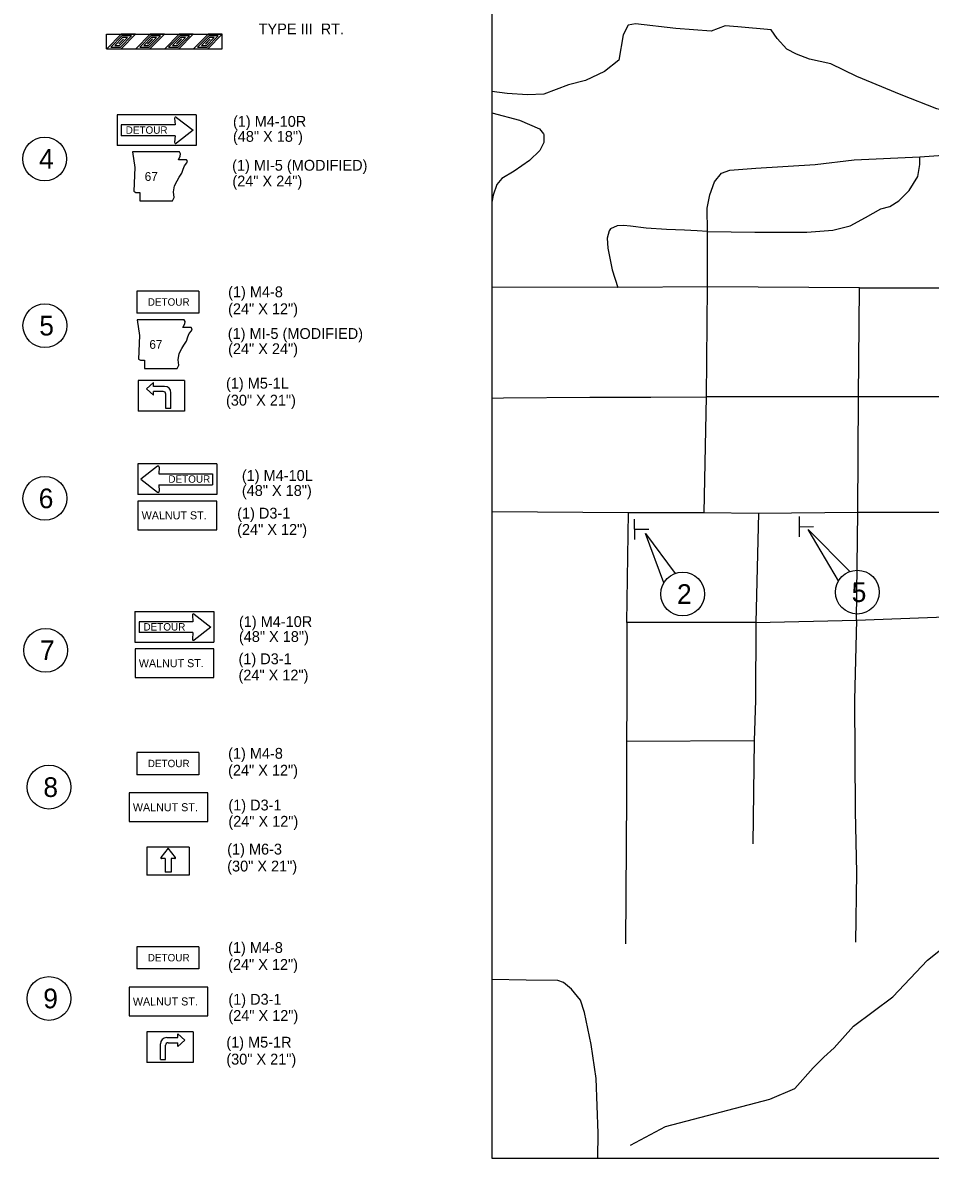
# Model space of a CAD drawing. Extents: x 988392 to 996681, y 1838707 to 1844440.
# Drawn here: x 988417 to 991180, y 1838707 to 1842166 of the extents above; entities that cross this region are included whole.
import ezdxf

# ---------------------------------------------------------------- set-up
doc = ezdxf.new("R2010")
doc.units = 0
for name, color, linetype in [('1', 7, 'Continuous'), ('21', 7, 'Continuous'), ('3', 7, 'Continuous'), ('8', 7, 'Continuous'), ('G-Border-Sheet', 7, 'Continuous'), ('Level 3', 7, 'Continuous'), ('Level 33', 7, 'Continuous'), ('Level 34', 7, 'Continuous'), ('Level 35', 7, 'Continuous'), ('Level 8', 7, 'Continuous')]:
    doc.layers.add(name, color=color, linetype=linetype)

msp = doc.modelspace()

# ---------------------------------------------------------------- linework, layer by layer
at = {"layer": '1'}
for p, q in [((988945.2, 1841885.5), (988704.8, 1841885.5)), ((988704.8, 1841885.5), (988704.8, 1841792.1)), ((988879.7, 1841874.6), (988881.3, 1841854.5)), ((988885, 1841877.5), (988936.2, 1841838)), ((988945.2, 1841885.5), (988945.2, 1841792.1)), ((988881.3, 1841854.5), (988717.3, 1841854.5)), ((988717.3, 1841854.5), (988717.3, 1841821.5)), ((988936.2, 1841838), (988885, 1841798.6)), ((988881.3, 1841821.5), (988717.3, 1841821.5)), ((988881.3, 1841821.5), (988879.7, 1841801.4)), ((988945.2, 1841792.1), (988704.8, 1841792.1)), ((988953.1, 1841348.4), (988764.2, 1841348.4)), ((988764.2, 1841348.4), (988764.2, 1841280.7)), ((988953.1, 1841348.4), (988953.1, 1841280.7)), ((988953.1, 1841280.7), (988764.2, 1841280.7)), ((988909.3, 1841075.5), (988768.9, 1841075.5)), ((988768.9, 1841075.5), (988768.9, 1840982.1)), ((988909.3, 1841075.5), (988909.3, 1840982.1)), ((988909.3, 1840982.1), (988768.9, 1840982.1)), ((989007.9, 1840822.5), (988767.5, 1840822.5)), ((988767.5, 1840822.5), (988767.5, 1840729.1)), ((988827.7, 1840814.5), (988776.5, 1840775)), ((988833, 1840811.6), (988831.4, 1840791.5)), ((989007.9, 1840822.5), (989007.9, 1840729.1)), ((988776.5, 1840775), (988827.7, 1840735.6)), ((988831.4, 1840791.5), (988995.4, 1840791.5)), ((988831.4, 1840758.5), (988995.4, 1840758.5)), ((988831.4, 1840758.5), (988833, 1840738.4)), ((988995.4, 1840791.5), (988995.4, 1840758.5)), ((989007.9, 1840729.1), (988767.5, 1840729.1)), ((988758.9, 1840372.3), (988999.3, 1840372.2)), ((988758.9, 1840372.3), (988758.9, 1840278.8)), ((988933.8, 1840361.4), (988935.4, 1840341.3)), ((988939.1, 1840364.2), (988990.3, 1840324.8)), ((988999.3, 1840372.2), (988999.3, 1840278.8)), ((988935.4, 1840341.3), (988771.4, 1840341.3)), ((988771.4, 1840341.3), (988771.4, 1840308.3)), ((988990.3, 1840324.8), (988939.1, 1840285.3)), ((988758.9, 1840278.8), (988999.3, 1840278.8)), ((988935.4, 1840308.3), (988771.4, 1840308.3)), ((988935.4, 1840308.3), (988933.8, 1840288.2)), ((988953.1, 1839942.8), (988764.2, 1839942.8)), ((988764.2, 1839942.8), (988764.2, 1839875)), ((988953.1, 1839942.8), (988953.1, 1839875)), ((988953.1, 1839875), (988764.2, 1839875)), ((988924.3, 1839654.9), (988795.6, 1839654.9)), ((988795.6, 1839654.9), (988795.6, 1839569.3)), ((988924.3, 1839654.9), (988924.3, 1839569.3)), ((988860, 1839651), (988838, 1839622.5)), ((988850.8, 1839620.4), (988839.6, 1839619.5)), ((988850.8, 1839620.4), (988850.8, 1839578.6)), ((988882, 1839622.5), (988860, 1839651)), ((988880.4, 1839619.5), (988869.2, 1839620.4)), ((988924.3, 1839569.3), (988795.6, 1839569.3)), ((988953.1, 1839351.2), (988764.2, 1839351.2)), ((988764.2, 1839351.2), (988764.2, 1839283.5)), ((988953.1, 1839351.2), (988953.1, 1839283.5)), ((988953.1, 1839283.5), (988764.2, 1839283.5)), ((988936, 1839092), (988795.6, 1839092)), ((988795.6, 1839092), (988795.6, 1838998.6)), ((988936, 1839092), (988936, 1838998.6)), ((988936, 1838998.6), (988795.6, 1838998.6))]:
    msp.add_line(p, q, dxfattribs=at)
msp.add_lwpolyline([(988869.2, 1839620.4), (988869.2, 1839578.6), (988850.8, 1839578.6)], dxfattribs=at)
at = {"layer": '21'}
for points in [[(988751.7, 1841772.4), (988758.8, 1841724.9), (988755.6, 1841652.8), (988761.9, 1841648.9), (988773.8, 1841648.9), (988773.8, 1841623.5), (988873.5, 1841623.4), (988878.3, 1841633.7), (988876.7, 1841650.3), (988879.1, 1841669.3), (988887.8, 1841684.4), (988893.4, 1841695.4), (988901.3, 1841707.3), (988906.1, 1841720), (988910, 1841730.3), (988917.2, 1841739), (988918.8, 1841744.5), (988915.6, 1841748.4), (988891, 1841748.5), (988896.6, 1841759.6), (988897.4, 1841766.7), (988894.1, 1841772.2)], [(988751.7, 1841772.4), (988758.8, 1841724.9), (988755.6, 1841652.8), (988761.9, 1841648.9), (988773.8, 1841648.9), (988773.8, 1841623.5), (988873.5, 1841623.4), (988878.3, 1841633.7), (988876.7, 1841650.3), (988879.1, 1841669.3), (988887.8, 1841684.4), (988893.4, 1841695.4), (988901.3, 1841707.3), (988906.1, 1841720), (988910, 1841730.3), (988917.2, 1841739), (988918.8, 1841744.5), (988915.6, 1841748.4), (988891, 1841748.5), (988896.6, 1841759.6), (988897.4, 1841766.7), (988894.1, 1841772.2)], [(988765.9, 1841261), (988772.9, 1841213.5), (988769.7, 1841141.4), (988776, 1841137.5), (988787.9, 1841137.5), (988787.9, 1841112.1), (988887.6, 1841112), (988892.4, 1841122.3), (988890.8, 1841138.9), (988893.2, 1841157.9), (988902, 1841173), (988907.5, 1841184), (988915.4, 1841195.9), (988920.2, 1841208.6), (988924.2, 1841218.9), (988931.3, 1841227.6), (988932.9, 1841233.1), (988929.7, 1841237.1), (988905.2, 1841237.1), (988910.7, 1841248.2), (988911.5, 1841255.3), (988908.3, 1841260.8)], [(988765.9, 1841261), (988772.9, 1841213.5), (988769.7, 1841141.4), (988776, 1841137.5), (988787.9, 1841137.5), (988787.9, 1841112.1), (988887.6, 1841112), (988892.4, 1841122.3), (988890.8, 1841138.9), (988893.2, 1841157.9), (988902, 1841173), (988907.5, 1841184), (988915.4, 1841195.9), (988920.2, 1841208.6), (988924.2, 1841218.9), (988931.3, 1841227.6), (988932.9, 1841233.1), (988929.7, 1841237.1), (988905.2, 1841237.1), (988910.7, 1841248.2), (988911.5, 1841255.3), (988908.3, 1841260.8)]]:
    msp.add_lwpolyline(points, close=True, dxfattribs=at)
at = {"layer": '3'}
for p, q in [((988672.5, 1842130.6), (989024.6, 1842130.6)), ((988672.5, 1842086.5), (988672.5, 1842130.6)), ((989024.6, 1842086.5), (989024.6, 1842130.6)), ((988672.5, 1842086.5), (989024.6, 1842086.5))]:
    msp.add_line(p, q, dxfattribs=at)
for points in [[(988760.6, 1842130.6), (988717.4, 1842130.4), (988673.4, 1842086.5), (988716.6, 1842086.5)], [(988748.5, 1842125.5), (988719.4, 1842125.4), (988685.5, 1842091.5), (988714.5, 1842091.5)], [(988697.5, 1842096.5), (988712.4, 1842096.5), (988736.4, 1842120.5), (988721.5, 1842120.5)], [(988724.3, 1842115.5), (988723.6, 1842115.5), (988709.6, 1842101.5), (988710.3, 1842101.5)], [(988848.6, 1842130.6), (988805.4, 1842130.4), (988761.4, 1842086.5), (988804.6, 1842086.5)], [(988836.5, 1842125.5), (988807.4, 1842125.4), (988773.5, 1842091.5), (988802.5, 1842091.5)], [(988785.5, 1842096.5), (988800.4, 1842096.5), (988824.4, 1842120.5), (988809.5, 1842120.5)], [(988812.3, 1842115.5), (988811.6, 1842115.5), (988797.6, 1842101.5), (988798.3, 1842101.5)], [(988936.6, 1842130.6), (988893.4, 1842130.4), (988849.4, 1842086.5), (988892.6, 1842086.5)], [(988924.5, 1842125.5), (988895.4, 1842125.4), (988861.5, 1842091.5), (988890.5, 1842091.5)], [(988873.5, 1842096.5), (988888.4, 1842096.5), (988912.4, 1842120.5), (988897.5, 1842120.5)], [(988900.3, 1842115.5), (988899.6, 1842115.5), (988885.6, 1842101.5), (988886.3, 1842101.5)], [(989024.6, 1842130.6), (988981.4, 1842130.4), (988937.4, 1842086.5), (988980.6, 1842086.5)], [(989012.5, 1842125.5), (988983.4, 1842125.4), (988949.5, 1842091.5), (988978.5, 1842091.5)], [(988961.5, 1842096.5), (988976.4, 1842096.5), (989000.4, 1842120.5), (988985.5, 1842120.5)], [(988988.3, 1842115.5), (988987.6, 1842115.5), (988973.6, 1842101.5), (988974.3, 1842101.5)]]:
    msp.add_lwpolyline(points, close=True, dxfattribs=at)
for centre, radius, start, end in [((988883, 1841874.9), 3.3, 52.3853, 184.5739), ((988883, 1841801.2), 3.3, 175.4261, 307.6112), ((988829.7, 1840811.9), 3.3, 355.4261, 127.6147), ((988829.7, 1840738.2), 3.3, 232.3888, 4.5739), ((988937.1, 1840361.6), 3.3, 52.3853, 184.5739), ((988937.1, 1840287.9), 3.3, 175.4261, 307.6112), ((988839.5, 1839621.4), 1.84, 142.3888, 274.5739), ((988880.5, 1839621.4), 1.84, 265.4261, 37.6147)]:
    msp.add_arc(centre, radius, start, end, dxfattribs=at)
at = {"layer": 'G-Border-Sheet'}
msp.add_lwpolyline([(995124.8, 1844439.6), (989844.9, 1844439.6), (989844.9, 1838706.8), (995124.8, 1838706.8)], close=True, dxfattribs=at)
at = {"layer": 'Level 3'}
for p, q in [((988794, 1841050.1), (988815.4, 1841069.4)), ((988815.4, 1841030.8), (988794, 1841050.1)), ((988815.4, 1841058), (988815.4, 1841069.4)), ((988849.3, 1841058), (988815.4, 1841058)), ((988845.1, 1841042.2), (988815.4, 1841042.2)), ((988815.4, 1841030.8), (988815.4, 1841042.2)), ((988868.6, 1840991), (988868.6, 1841038.7)), ((988852.8, 1840991), (988852.8, 1841034.5)), ((988868.6, 1840991), (988852.8, 1840991)), ((990781.9, 1840599.8), (990781.5, 1840661.7)), ((990280.5, 1840592), (990280.1, 1840653.9)), ((990281.2, 1840622.8), (990323.5, 1840623.1)), ((990782.6, 1840630.6), (990824.8, 1840630.9)), ((988855.6, 1839074.4), (988889.5, 1839074.4)), ((988889.5, 1839074.4), (988889.5, 1839085.8)), ((988910.9, 1839066.5), (988889.5, 1839085.8)), ((988889.5, 1839047.2), (988910.9, 1839066.5)), ((988836.4, 1839007.4), (988836.4, 1839055.2)), ((988852.2, 1839007.4), (988852.2, 1839050.9)), ((988859.9, 1839058.7), (988889.5, 1839058.7)), ((988889.5, 1839047.2), (988889.5, 1839058.7)), ((988836.4, 1839007.4), (988852.2, 1839007.4))]:
    msp.add_line(p, q, dxfattribs=at)
for centre, radius, start, end in [((988845.1, 1841034.5), 7.71, 0, 90), ((988849.3, 1841038.7), 19.3, 0, 90), ((988855.6, 1839055.2), 19.3, 90, 180), ((988859.9, 1839050.9), 7.71, 90, 180)]:
    msp.add_arc(centre, radius, start, end, dxfattribs=at)
at = {"layer": 'Level 33'}
for points in [[(989844.9, 1841891.5), (989929.7, 1841868.5), (989990.2, 1841842.7), (990002.6, 1841827), (990003.7, 1841824.8), (990003.7, 1841801.2), (989991.4, 1841776.6), (989960, 1841746.3), (989912.9, 1841713.8), (989876, 1841691.3), (989860.3, 1841673.4), (989849.1, 1841640.9), (989844.9, 1841618.7)], [(990491.5, 1840673.8), (990498.7, 1841026.3), (990501.9, 1841361.3), (990501.9, 1841530.1), (990500.8, 1841600.7), (990508.6, 1841641.1), (990523.2, 1841681.5), (990544.4, 1841707.2), (990570.2, 1841716.2), (990648.6, 1841722.9), (990830.1, 1841734.2), (990948.9, 1841747.6), (991148.3, 1841757.7), (991332.5, 1841770.5)], [(990501.9, 1841529.8), (990646.4, 1841527.8), (990804.3, 1841527.8), (990883.9, 1841533.4), (990936.5, 1841546.9), (990982.5, 1841572.7), (991029.5, 1841598.5), (991057.5, 1841606.3), (991084.4, 1841623.2), (991115.8, 1841654.5), (991142.7, 1841697.2), (991148.3, 1841734.2), (991148.3, 1841757.7)], [(990501.9, 1841530.1), (990470.8, 1841532.2), (990432.2, 1841533.9), (990377.3, 1841536.1), (990315.7, 1841539.5), (990267.5, 1841545.6), (990246.2, 1841547.9), (990227.2, 1841546.7), (990207, 1841537.8), (990202.5, 1841532.2), (990196.4, 1841509.7), (990198.1, 1841479.5), (990211.5, 1841413.3), (990228.5, 1841359.6)], [(990501.9, 1841361.3), (990228.5, 1841359.6), (989844.9, 1841360.7)], [(990964.8, 1841357.7), (990501.9, 1841361.3)], [(990959.4, 1840674.9), (990961.4, 1841026.3), (990964.8, 1841357.7)], [(990964.8, 1841357.7), (991322.2, 1841357.7)], [(989844.9, 1841022.4), (989880.5, 1841022.7), (990143.7, 1841024.9), (990329.7, 1841024.9), (990498.7, 1841026.3)], [(991318.8, 1841026.3), (990961.4, 1841026.3), (990498.7, 1841026.3)], [(989844.9, 1840676.8), (990261.8, 1840673.8), (990491.5, 1840673.8), (990657.3, 1840671.6), (990959.4, 1840674.9), (991315.6, 1840674.9), (991751.2, 1840677)], [(990648.7, 1840338.5), (990256.7, 1840338.5), (990261.8, 1840673.8)], [(990657.3, 1840671.6), (990648.7, 1840338.5)], [(990955.7, 1840346.4), (990959.4, 1840674.9)], [(990648.7, 1840338.5), (990955.7, 1840346.4), (991306.3, 1840358.7), (991748.9, 1840356.5), (991751.2, 1840400.1)], [(990955.7, 1840346.4), (990949.9, 1840103.7), (990951, 1839764), (990955.5, 1839576.7), (990952.1, 1839365.3)], [(990256.7, 1840338.5), (990256.7, 1840099.1), (990255.5, 1839975.9), (990255.5, 1839809.9), (990252.2, 1839359.6)], [(990648.7, 1840338.5), (990647.6, 1840102.6), (990644.3, 1839978.1), (990639.8, 1839664.2)], [(990644.3, 1839978.1), (990255.5, 1839975.9)]]:
    msp.add_lwpolyline(points, dxfattribs=at)
at = {"layer": 'Level 34'}
msp.add_lwpolyline([(990168.4, 1838706.8), (990169.3, 1838783.5), (990162.6, 1838949.4), (990148.1, 1839053), (990127, 1839151), (990114.8, 1839188.9), (990088.1, 1839222.3), (990063.6, 1839242.3), (990045.8, 1839247.9), (989950.1, 1839249), (989844.9, 1839251.7)], dxfattribs=at)
at = {"layer": 'Level 35'}
for points in [[(990282.4, 1842162.6), (990260.4, 1842158.4), (990245.7, 1842129.2), (990232.5, 1842052.1), (990188.6, 1842017.5), (990130.2, 1841989.6), (990078.4, 1841976.3), (990004.1, 1841948.4), (989953.6, 1841945.8), (989892.5, 1841949.8), (989844.9, 1841956.7)], [(990695.4, 1842144), (990594.5, 1842153.3), (990555.9, 1842156), (990513.5, 1842140), (990405.9, 1842148), (990282.4, 1842162.6)], [(990877.3, 1842040.8), (990812.2, 1842055), (990772.4, 1842069.6), (990743.2, 1842085.6), (990714, 1842117.5), (990695.4, 1842144)], [(992581.4, 1841048.3), (992531.2, 1841104.9), (992456.9, 1841168.7), (992402.4, 1841216.6), (992328.1, 1841264.4), (992211.2, 1841310.9), (992074.4, 1841382.7), (992025.3, 1841415.9), (991847.4, 1841554.8), (991759.7, 1841613.3), (991689.3, 1841663.8), (991598.1, 1841710.3), (991562.3, 1841728.9), (991515.8, 1841764.8), (991430.8, 1841823.3), (991348.5, 1841861.9), (991327.2, 1841864), (991247.5, 1841891.9), (991200, 1841903.9), (991091.8, 1841946.4), (990957, 1842002.2), (990877.3, 1842040.8)], [(990691.9, 1838887), (990768.1, 1838919.6), (990823.8, 1838982.2), (990856.4, 1839014.9), (990887.7, 1839043.5), (990946.2, 1839108.8), (991065.8, 1839198.6), (991171.8, 1839310.2), (991250.7, 1839372.8)], [(990267.2, 1838746.4), (990373.8, 1838804), (990691.9, 1838887)]]:
    msp.add_lwpolyline(points, dxfattribs=at)
at = {"layer": 'Level 8'}
for points in [[(989007.7, 1840708.8), (988768, 1840708.8), (988768, 1840621.5), (989007.7, 1840621.5)], [(988999.1, 1840258.5), (988759.3, 1840258.5), (988759.3, 1840171.3), (988999.1, 1840171.3)], [(988981, 1839819.7), (988741.2, 1839819.7), (988741.2, 1839732.5), (988981, 1839732.5)], [(988981, 1839228.1), (988741.2, 1839228.1), (988741.2, 1839140.9), (988981, 1839140.9)]]:
    msp.add_lwpolyline(points, close=True, dxfattribs=at)
for points in [[(990900.8, 1840465.7), (990808.8, 1840622.3), (990935.5, 1840494.1)], [(990369.1, 1840459.8), (990312.8, 1840610.1), (990403.7, 1840488.2)]]:
    msp.add_lwpolyline(points, dxfattribs=at)
for centre in [(988483.9, 1841750.9), (988484.7, 1841243), (988484.7, 1840716.9), (990426.1, 1840425.4), (990957.9, 1840431.3), (988486.9, 1840254.2), (988497.1, 1839837.4), (988497.1, 1839193.6)]:
    msp.add_circle(centre, 66.7, dxfattribs=at)

# ---------------------------------------------------------------- texts
at = {"layer": '3'}
for p in [(988730.8, 1841827.5), (988860.7, 1840764.5), (988784.9, 1840314.3)]:
    msp.add_text('DETOUR', height=22.56, dxfattribs=at).set_placement(p)
for p in [(988798, 1841303.8), (988798, 1839898.2), (988798, 1839306.6)]:
    msp.add_text('DETOUR', height=22.56, rotation=360, dxfattribs=at).set_placement(p)
at = {"layer": '8'}
for s, p in [('TYPE III  RT.', (989135.5, 1842130.3)), ('(1) D3-1', (989070.1, 1840655.3)), ('(24" X 12")', (989070.1, 1840605.8)), ('(1) D3-1', (989074.2, 1840211.7)), ('(24" X 12")', (989074.2, 1840162.2)), ('(1) D3-1', (989043.3, 1839766.3)), ('(24" X 12")', (989043.3, 1839716.8)), ('(1) D3-1', (989043.3, 1839174.7)), ('(24" X 12")', (989043.3, 1839125.2))]:
    msp.add_text(s, height=33, rotation=360, dxfattribs=at).set_placement(p)
for p in [(988788.7, 1841683.9), (988802.8, 1841172.5)]:
    msp.add_text('67', height=26.68, dxfattribs=at).set_placement(p)
at = {"layer": 'Level 8'}
for s, height, rotation, p in [('(1) M4-10R', 33, 0, (989057.3, 1841848.7)), ('(48" X 18")', 32.999, 0, (989057.3, 1841803)), ('(1) MI-5 (MODIFIED)', 33, 360, (989054.8, 1841715)), ('(24" X 24")', 32.999, 0, (989055.5, 1841667)), ('(1) M4-8', 33, 0, (989042.5, 1841329.5)), ('(24" X 12")', 32.999, 0, (989042.5, 1841277.9)), ('(1) MI-5 (MODIFIED)', 33, 360, (989041.5, 1841202.5)), ('(24" X 24")', 32.999, 0, (989042.5, 1841156.2)), ('(1) M5-1L', 33, 0, (989036.1, 1841051.1)), ('(30" X 21")', 32.999, 0, (989036.1, 1840999.5)), ('(1) M4-10L', 33, 0, (989084.4, 1840770.1)), ('(48" X 18")', 32.999, 0, (989084.4, 1840724.4)), ('WALNUT ST.', 24.43, 0.0858, (988779.4, 1840652.8)), ('(1) M4-10R', 33, 0, (989075.5, 1840325.1)), ('(48" X 18")', 32.999, 0, (989075.5, 1840279.5)), ('WALNUT ST.', 24.43, 0.0858, (988770.7, 1840202.5)), ('(1) M4-8', 33, 0, (989042.5, 1839923.8)), ('(24" X 12")', 32.999, 0, (989042.5, 1839872.3)), ('WALNUT ST.', 24.43, 0.0858, (988752.6, 1839763.7)), ('(1) M6-3', 33, 0, (989039.8, 1839632)), ('(30" X 21")', 32.999, 0, (989039.8, 1839580.4)), ('(1) M4-8', 33, 0, (989042.5, 1839332.2)), ('(24" X 12")', 32.999, 0, (989042.5, 1839280.7)), ('WALNUT ST.', 24.43, 0.0858, (988752.6, 1839172.1)), ('(1) M5-1R', 33, 0, (989037.1, 1839043.9)), ('(30" X 21")', 32.999, 0, (989037.1, 1838992.3))]:
    msp.add_text(s, height=height, rotation=rotation, dxfattribs=at).set_placement(p)
for s, p in [('4', (988466.9, 1841720.9)), ('5', (988467.7, 1841213)), ('6', (988466, 1840686.9)), ('2', (990409.1, 1840395.4)), ('5', (990940.9, 1840401.3)), ('7', (988469.9, 1840224.2)), ('8', (988480.1, 1839807.4)), ('9', (988479.8, 1839163.6))]:
    msp.add_text(s, height=60, dxfattribs=at).set_placement(p)

doc.saveas('drawing.dxf')
